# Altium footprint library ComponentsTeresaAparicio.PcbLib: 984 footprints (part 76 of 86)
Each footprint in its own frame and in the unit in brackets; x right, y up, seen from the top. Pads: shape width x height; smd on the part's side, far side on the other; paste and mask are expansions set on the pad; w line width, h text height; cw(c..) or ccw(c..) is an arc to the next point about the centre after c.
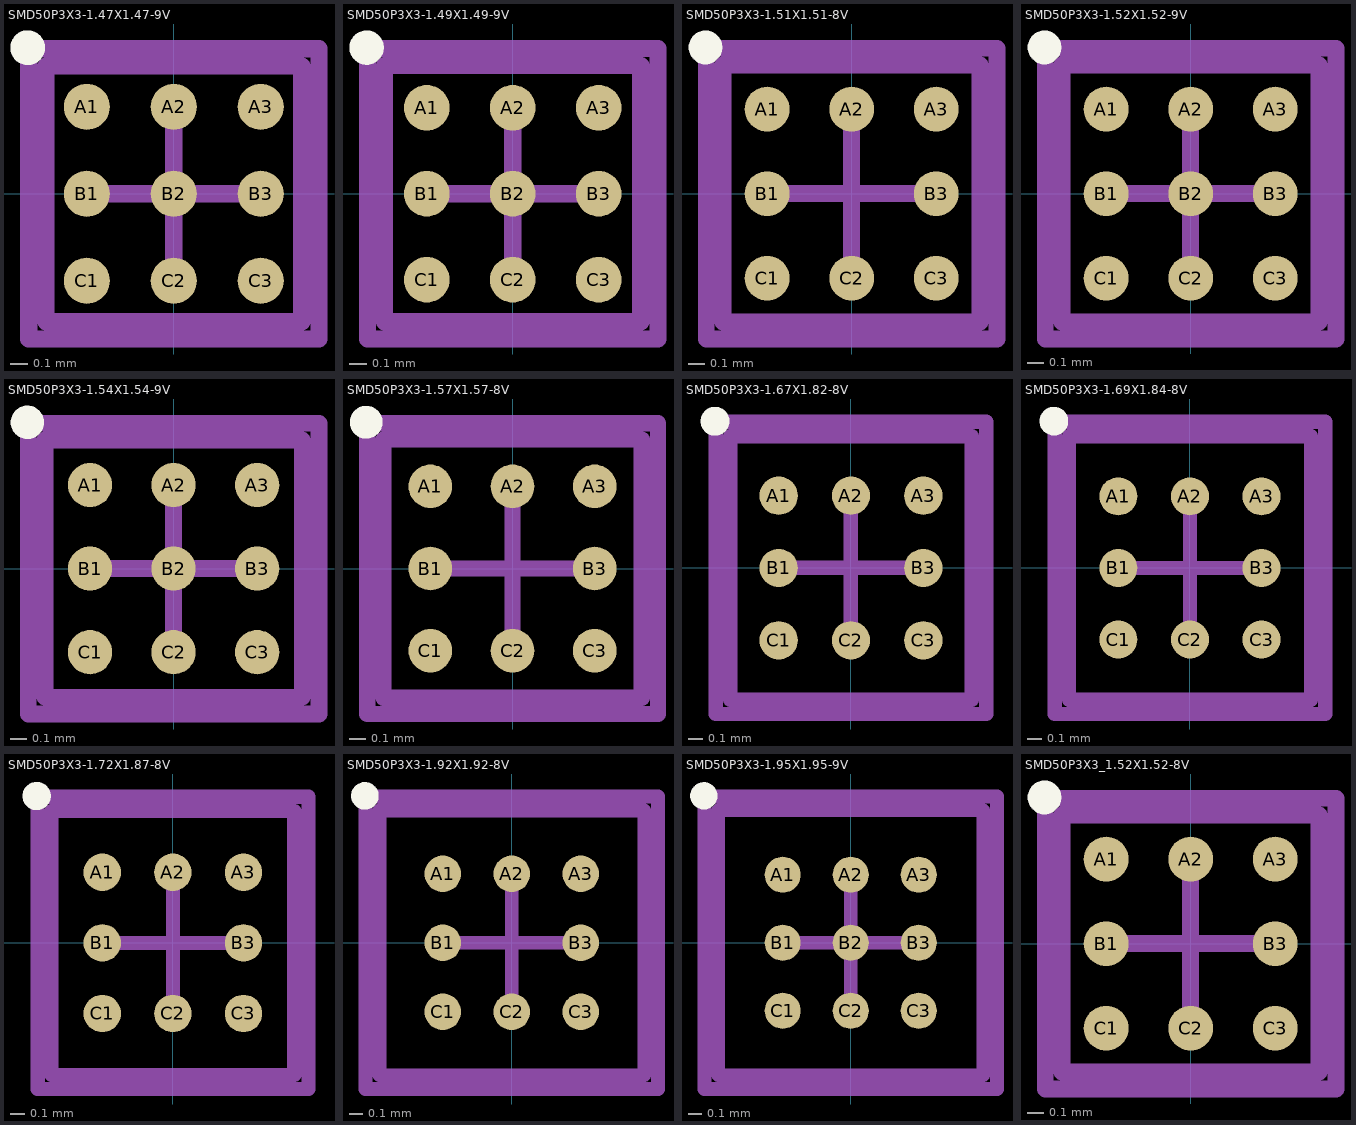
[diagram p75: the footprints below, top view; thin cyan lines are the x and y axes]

## SMD50P3X3-1.47X1.47-9V [mm] "Micro SMD, 9-Leads, Body 1.47x1.47mm, Pitch 0.5mm, NSC Recommended"
height 0.68
pads (9):
  round 0.265 smd paste-0.132 mask+0.05: A1(-0.5,0.5) A2(0,0.5) A3(0.5,0.5) B1(-0.5,0) B2(0,0) B3(0.5,0) C1(-0.5,-0.5) C2(0,-0.5) C3(0.5,-0.5)
Top Overlay:
  circle w0.1: c-0.84,0.84 r0.05
Top Paste:
  circle w0.05: c0.075,-0.6 r0.025
  circle w0.05: c-0.075,-0.45 r0.025
  circle w0.05: c-0.075,-0.6 r0.025
  circle w0.05: c0.075,-0.45 r0.025
  circle w0.05: c-0.6,-0.075 r0.025
  circle w0.05: c-0.45,0.075 r0.025
  circle w0.05: c-0.6,0.075 r0.025
  circle w0.05: c-0.45,-0.075 r0.025
  circle w0.05: c-0.075,0.6 r0.025
  circle w0.05: c0.075,0.45 r0.025
  circle w0.05: c0.075,0.6 r0.025
  circle w0.05: c-0.075,0.45 r0.025
  circle w0.05: c0.6,0.075 r0.025
  circle w0.05: c0.45,-0.075 r0.025
  circle w0.05: c0.6,-0.075 r0.025
  circle w0.05: c0.45,0.075 r0.025
  circle w0.05: c-0.45,0.45 r0.025
  circle w0.05: c-0.6,0.6 r0.025
  circle w0.05: c-0.45,0.6 r0.025
  circle w0.05: c-0.6,0.45 r0.025
  circle w0.05: c-0.45,-0.45 r0.025
  circle w0.05: c-0.6,-0.6 r0.025
  circle w0.05: c-0.6,-0.45 r0.025
  circle w0.05: c-0.45,-0.6 r0.025
  circle w0.05: c0.45,-0.45 r0.025
  circle w0.05: c0.6,-0.6 r0.025
  circle w0.05: c0.45,-0.6 r0.025
  circle w0.05: c0.6,-0.45 r0.025
  circle w0.05: c0.45,0.45 r0.025
  circle w0.05: c0.6,0.6 r0.025
  circle w0.05: c0.6,0.45 r0.025
  circle w0.05: c0.45,0.6 r0.025
  circle w0.05: c0.075,-0.075 r0.025
  circle w0.05: c-0.075,0.075 r0.025
  circle w0.05: c-0.075,-0.075 r0.025
  circle w0.05: c0.075,0.075 r0.025
  rectangle: -0.075,-0.45 0.075,-0.4
  region: -0.075,-0.6 -0.075,-0.45 -0.125,-0.45 -0.125,-0.6
  region: 0.075,-0.6 -0.075,-0.6 -0.075,-0.65 0.075,-0.65
  region: 0.075,-0.45 0.075,-0.6 0.125,-0.6 0.125,-0.45
  region: 0.075,-0.6 0.075,-0.45 -0.075,-0.45 -0.075,-0.6
  region: -0.45,0.075 -0.45,-0.075 -0.4,-0.075 -0.4,0.075
  rectangle: -0.6,0.075 -0.45,0.125
  region: -0.6,-0.075 -0.6,0.075 -0.65,0.075 -0.65,-0.075
  region: -0.45,-0.075 -0.6,-0.075 -0.6,-0.125 -0.45,-0.125
  rectangle: -0.6,-0.075 -0.45,0.075
  region: 0.075,0.45 -0.075,0.45 -0.075,0.4 0.075,0.4
  region: 0.075,0.6 0.075,0.45 0.125,0.45 0.125,0.6
  rectangle: -0.075,0.6 0.075,0.65
  region: -0.075,0.45 -0.075,0.6 -0.125,0.6 -0.125,0.45
  region: -0.075,0.6 -0.075,0.45 0.075,0.45 0.075,0.6
  region: 0.45,-0.075 0.45,0.075 0.4,0.075 0.4,-0.075
  region: 0.6,-0.075 0.45,-0.075 0.45,-0.125 0.6,-0.125
  region: 0.6,0.075 0.6,-0.075 0.65,-0.075 0.65,0.075
  rectangle: 0.45,0.075 0.6,0.125
  region: 0.6,0.075 0.45,0.075 0.45,-0.075 0.6,-0.075
  rectangle: -0.6,0.45 -0.45,0.6
  region: -0.45,0.45 -0.6,0.45 -0.6,0.4 -0.45,0.4
  region: -0.6,0.45 -0.6,0.6 -0.65,0.6 -0.65,0.45
  rectangle: -0.6,0.6 -0.45,0.65
  region: -0.45,0.6 -0.45,0.45 -0.4,0.45 -0.4,0.6
  region: -0.45,-0.6 -0.45,-0.45 -0.6,-0.45 -0.6,-0.6
  region: -0.45,-0.45 -0.45,-0.6 -0.4,-0.6 -0.4,-0.45
  region: -0.45,-0.6 -0.6,-0.6 -0.6,-0.65 -0.45,-0.65
  region: -0.6,-0.6 -0.6,-0.45 -0.65,-0.45 -0.65,-0.6
  rectangle: -0.6,-0.45 -0.45,-0.4
  region: 0.6,-0.45 0.45,-0.45 0.45,-0.6 0.6,-0.6
  rectangle: 0.45,-0.45 0.6,-0.4
  region: 0.6,-0.45 0.6,-0.6 0.65,-0.6 0.65,-0.45
  region: 0.6,-0.6 0.45,-0.6 0.45,-0.65 0.6,-0.65
  region: 0.45,-0.6 0.45,-0.45 0.4,-0.45 0.4,-0.6
  region: 0.45,0.6 0.45,0.45 0.6,0.45 0.6,0.6
  region: 0.45,0.45 0.45,0.6 0.4,0.6 0.4,0.45
  rectangle: 0.45,0.6 0.6,0.65
  region: 0.6,0.6 0.6,0.45 0.65,0.45 0.65,0.6
  region: 0.6,0.45 0.45,0.45 0.45,0.4 0.6,0.4
  region: -0.075,0.075 -0.075,-0.075 0.075,-0.075 0.075,0.075
  region: 0.125,-0.075 0.125,0.075 0.075,0.075 0.075,-0.075
  region: 0.075,0.125 -0.075,0.125 -0.075,0.075 0.075,0.075
  region: -0.125,0.075 -0.125,-0.075 -0.075,-0.075 -0.075,0.075
  rectangle: -0.075,-0.125 0.075,-0.075
Mechanical 13:
  lines w0.1: -0.735,-0.735 0.735,-0.735 0.735,0.735 -0.735,0.735 -0.735,-0.735
Mechanical 15:
  lines w0.1: -0.5,0 0.5,0 ; 0,-0.5 0,0.5 ; -0.835,-0.835 0.835,-0.835 0.835,0.835 -0.835,0.835 -0.835,-0.835
3D body: height 0.68, standoff 0, extent -0.734,-0.734 0.734,0.734

## SMD50P3X3-1.49X1.49-9V [mm] "Micro SMD, 9-Leads, Body 1.49x1.49mm, Pitch 0.5mm, NSC Recommended"
height 0.68
pads (9):
  round 0.265 smd paste-0.132 mask+0.05: A1(-0.5,0.5) A2(0,0.5) A3(0.5,0.5) B1(-0.5,0) B2(0,0) B3(0.5,0) C1(-0.5,-0.5) C2(0,-0.5) C3(0.5,-0.5)
Top Overlay:
  circle w0.1: c-0.85,0.85 r0.05
Top Paste:
  circle w0.05: c-0.6,-0.075 r0.025
  circle w0.05: c-0.45,0.075 r0.025
  circle w0.05: c-0.6,0.075 r0.025
  circle w0.05: c-0.45,-0.075 r0.025
  circle w0.05: c-0.075,0.6 r0.025
  circle w0.05: c0.075,0.45 r0.025
  circle w0.05: c0.075,0.6 r0.025
  circle w0.05: c-0.075,0.45 r0.025
  circle w0.05: c0.6,0.075 r0.025
  circle w0.05: c0.45,-0.075 r0.025
  circle w0.05: c0.6,-0.075 r0.025
  circle w0.05: c0.45,0.075 r0.025
  circle w0.05: c0.075,-0.6 r0.025
  circle w0.05: c-0.075,-0.45 r0.025
  circle w0.05: c-0.075,-0.6 r0.025
  circle w0.05: c0.075,-0.45 r0.025
  circle w0.05: c0.45,0.45 r0.025
  circle w0.05: c0.6,0.6 r0.025
  circle w0.05: c0.6,0.45 r0.025
  circle w0.05: c0.45,0.6 r0.025
  circle w0.05: c-0.45,0.45 r0.025
  circle w0.05: c-0.6,0.6 r0.025
  circle w0.05: c-0.45,0.6 r0.025
  circle w0.05: c-0.6,0.45 r0.025
  circle w0.05: c-0.45,-0.45 r0.025
  circle w0.05: c-0.6,-0.6 r0.025
  circle w0.05: c-0.6,-0.45 r0.025
  circle w0.05: c-0.45,-0.6 r0.025
  circle w0.05: c0.45,-0.45 r0.025
  circle w0.05: c0.6,-0.6 r0.025
  circle w0.05: c0.45,-0.6 r0.025
  circle w0.05: c0.6,-0.45 r0.025
  circle w0.05: c0.075,-0.075 r0.025
  circle w0.05: c-0.075,0.075 r0.025
  circle w0.05: c-0.075,-0.075 r0.025
  circle w0.05: c0.075,0.075 r0.025
  region: -0.45,0.075 -0.45,-0.075 -0.4,-0.075 -0.4,0.075
  rectangle: -0.6,0.075 -0.45,0.125
  region: -0.6,-0.075 -0.6,0.075 -0.65,0.075 -0.65,-0.075
  region: -0.45,-0.075 -0.6,-0.075 -0.6,-0.125 -0.45,-0.125
  rectangle: -0.6,-0.075 -0.45,0.075
  region: 0.075,0.45 -0.075,0.45 -0.075,0.4 0.075,0.4
  region: 0.075,0.6 0.075,0.45 0.125,0.45 0.125,0.6
  rectangle: -0.075,0.6 0.075,0.65
  region: -0.075,0.45 -0.075,0.6 -0.125,0.6 -0.125,0.45
  region: -0.075,0.6 -0.075,0.45 0.075,0.45 0.075,0.6
  region: 0.45,-0.075 0.45,0.075 0.4,0.075 0.4,-0.075
  region: 0.6,-0.075 0.45,-0.075 0.45,-0.125 0.6,-0.125
  region: 0.6,0.075 0.6,-0.075 0.65,-0.075 0.65,0.075
  rectangle: 0.45,0.075 0.6,0.125
  region: 0.6,0.075 0.45,0.075 0.45,-0.075 0.6,-0.075
  rectangle: -0.075,-0.45 0.075,-0.4
  region: -0.075,-0.6 -0.075,-0.45 -0.125,-0.45 -0.125,-0.6
  region: 0.075,-0.6 -0.075,-0.6 -0.075,-0.65 0.075,-0.65
  region: 0.075,-0.45 0.075,-0.6 0.125,-0.6 0.125,-0.45
  region: 0.075,-0.6 0.075,-0.45 -0.075,-0.45 -0.075,-0.6
  region: 0.45,0.6 0.45,0.45 0.6,0.45 0.6,0.6
  region: 0.45,0.45 0.45,0.6 0.4,0.6 0.4,0.45
  rectangle: 0.45,0.6 0.6,0.65
  region: 0.6,0.6 0.6,0.45 0.65,0.45 0.65,0.6
  region: 0.6,0.45 0.45,0.45 0.45,0.4 0.6,0.4
  rectangle: -0.6,0.45 -0.45,0.6
  region: -0.45,0.45 -0.6,0.45 -0.6,0.4 -0.45,0.4
  region: -0.6,0.45 -0.6,0.6 -0.65,0.6 -0.65,0.45
  rectangle: -0.6,0.6 -0.45,0.65
  region: -0.45,0.6 -0.45,0.45 -0.4,0.45 -0.4,0.6
  region: -0.45,-0.6 -0.45,-0.45 -0.6,-0.45 -0.6,-0.6
  region: -0.45,-0.45 -0.45,-0.6 -0.4,-0.6 -0.4,-0.45
  region: -0.45,-0.6 -0.6,-0.6 -0.6,-0.65 -0.45,-0.65
  region: -0.6,-0.6 -0.6,-0.45 -0.65,-0.45 -0.65,-0.6
  rectangle: -0.6,-0.45 -0.45,-0.4
  region: 0.6,-0.45 0.45,-0.45 0.45,-0.6 0.6,-0.6
  rectangle: 0.45,-0.45 0.6,-0.4
  region: 0.6,-0.45 0.6,-0.6 0.65,-0.6 0.65,-0.45
  region: 0.6,-0.6 0.45,-0.6 0.45,-0.65 0.6,-0.65
  region: 0.45,-0.6 0.45,-0.45 0.4,-0.45 0.4,-0.6
  region: -0.075,0.075 -0.075,-0.075 0.075,-0.075 0.075,0.075
  region: 0.125,-0.075 0.125,0.075 0.075,0.075 0.075,-0.075
  region: 0.075,0.125 -0.075,0.125 -0.075,0.075 0.075,0.075
  region: -0.125,0.075 -0.125,-0.075 -0.075,-0.075 -0.075,0.075
  rectangle: -0.075,-0.125 0.075,-0.075
Mechanical 13:
  lines w0.1: -0.745,-0.745 0.745,-0.745 0.745,0.745 -0.745,0.745 -0.745,-0.745
Mechanical 15:
  lines w0.1: -0.5,0 0.5,0 ; 0,-0.5 0,0.5 ; -0.845,-0.845 0.845,-0.845 0.845,0.845 -0.845,0.845 -0.845,-0.845
3D body: height 0.68, standoff 0, extent -0.744,-0.744 0.744,0.744

## SMD50P3X3-1.51X1.51-8V [mm] "Micro SMD, 8-Leads, Body 1.51x1.51mm, Pitch 0.5mm, NSC Recommended"
height 1.1
pads (8):
  round 0.265 smd paste-0.132 mask+0.05: A1(-0.5,0.5) A2(0,0.5) A3(0.5,0.5) B1(-0.5,0) B3(0.5,0) C1(-0.5,-0.5) C2(0,-0.5) C3(0.5,-0.5)
Top Overlay:
  circle w0.1: c-0.865,0.865 r0.05
Top Paste:
  circle w0.05: c-0.075,0.6 r0.025
  circle w0.05: c0.075,0.45 r0.025
  circle w0.05: c0.075,0.6 r0.025
  circle w0.05: c-0.075,0.45 r0.025
  circle w0.05: c0.6,0.075 r0.025
  circle w0.05: c0.45,-0.075 r0.025
  circle w0.05: c0.6,-0.075 r0.025
  circle w0.05: c0.45,0.075 r0.025
  circle w0.05: c0.075,-0.6 r0.025
  circle w0.05: c-0.075,-0.45 r0.025
  circle w0.05: c-0.075,-0.6 r0.025
  circle w0.05: c0.075,-0.45 r0.025
  circle w0.05: c-0.6,-0.075 r0.025
  circle w0.05: c-0.45,0.075 r0.025
  circle w0.05: c-0.6,0.075 r0.025
  circle w0.05: c-0.45,-0.075 r0.025
  circle w0.05: c0.45,0.45 r0.025
  circle w0.05: c0.6,0.6 r0.025
  circle w0.05: c0.6,0.45 r0.025
  circle w0.05: c0.45,0.6 r0.025
  circle w0.05: c0.45,-0.45 r0.025
  circle w0.05: c0.6,-0.6 r0.025
  circle w0.05: c0.45,-0.6 r0.025
  circle w0.05: c0.6,-0.45 r0.025
  circle w0.05: c-0.45,-0.45 r0.025
  circle w0.05: c-0.6,-0.6 r0.025
  circle w0.05: c-0.6,-0.45 r0.025
  circle w0.05: c-0.45,-0.6 r0.025
  circle w0.05: c-0.45,0.45 r0.025
  circle w0.05: c-0.6,0.6 r0.025
  circle w0.05: c-0.45,0.6 r0.025
  circle w0.05: c-0.6,0.45 r0.025
  region: 0.075,0.45 -0.075,0.45 -0.075,0.4 0.075,0.4
  region: 0.075,0.6 0.075,0.45 0.125,0.45 0.125,0.6
  rectangle: -0.075,0.6 0.075,0.65
  region: -0.075,0.45 -0.075,0.6 -0.125,0.6 -0.125,0.45
  region: -0.075,0.6 -0.075,0.45 0.075,0.45 0.075,0.6
  region: 0.45,-0.075 0.45,0.075 0.4,0.075 0.4,-0.075
  region: 0.6,-0.075 0.45,-0.075 0.45,-0.125 0.6,-0.125
  region: 0.6,0.075 0.6,-0.075 0.65,-0.075 0.65,0.075
  rectangle: 0.45,0.075 0.6,0.125
  region: 0.6,0.075 0.45,0.075 0.45,-0.075 0.6,-0.075
  rectangle: -0.075,-0.45 0.075,-0.4
  region: -0.075,-0.6 -0.075,-0.45 -0.125,-0.45 -0.125,-0.6
  region: 0.075,-0.6 -0.075,-0.6 -0.075,-0.65 0.075,-0.65
  region: 0.075,-0.45 0.075,-0.6 0.125,-0.6 0.125,-0.45
  region: 0.075,-0.6 0.075,-0.45 -0.075,-0.45 -0.075,-0.6
  region: -0.45,0.075 -0.45,-0.075 -0.4,-0.075 -0.4,0.075
  rectangle: -0.6,0.075 -0.45,0.125
  region: -0.6,-0.075 -0.6,0.075 -0.65,0.075 -0.65,-0.075
  region: -0.45,-0.075 -0.6,-0.075 -0.6,-0.125 -0.45,-0.125
  rectangle: -0.6,-0.075 -0.45,0.075
  region: 0.45,0.6 0.45,0.45 0.6,0.45 0.6,0.6
  region: 0.45,0.45 0.45,0.6 0.4,0.6 0.4,0.45
  rectangle: 0.45,0.6 0.6,0.65
  region: 0.6,0.6 0.6,0.45 0.65,0.45 0.65,0.6
  region: 0.6,0.45 0.45,0.45 0.45,0.4 0.6,0.4
  region: 0.6,-0.45 0.45,-0.45 0.45,-0.6 0.6,-0.6
  rectangle: 0.45,-0.45 0.6,-0.4
  region: 0.6,-0.45 0.6,-0.6 0.65,-0.6 0.65,-0.45
  region: 0.6,-0.6 0.45,-0.6 0.45,-0.65 0.6,-0.65
  region: 0.45,-0.6 0.45,-0.45 0.4,-0.45 0.4,-0.6
  region: -0.45,-0.6 -0.45,-0.45 -0.6,-0.45 -0.6,-0.6
  region: -0.45,-0.45 -0.45,-0.6 -0.4,-0.6 -0.4,-0.45
  region: -0.45,-0.6 -0.6,-0.6 -0.6,-0.65 -0.45,-0.65
  region: -0.6,-0.6 -0.6,-0.45 -0.65,-0.45 -0.65,-0.6
  rectangle: -0.6,-0.45 -0.45,-0.4
  rectangle: -0.6,0.45 -0.45,0.6
  region: -0.45,0.45 -0.6,0.45 -0.6,0.4 -0.45,0.4
  region: -0.6,0.45 -0.6,0.6 -0.65,0.6 -0.65,0.45
  rectangle: -0.6,0.6 -0.45,0.65
  region: -0.45,0.6 -0.45,0.45 -0.4,0.45 -0.4,0.6
Mechanical 13:
  lines w0.1: -0.76,-0.76 -0.76,0.76 0.76,0.76 0.76,-0.76 -0.76,-0.76
Mechanical 15:
  lines w0.1: -0.5,0 0.5,0 ; 0,-0.5 0,0.5 ; -0.86,-0.86 -0.86,0.86 0.86,0.86 0.86,-0.86 -0.86,-0.86
3D body: height 1.1, standoff 0, extent -0.759,-0.759 0.759,0.759

## SMD50P3X3-1.52X1.52-9V [mm] "Micro SMD, 9-Leads, Body 1.52x1.52mm, Pitch 0.5mm, NSC Recommended"
height 0.68
pads (9):
  round 0.265 smd paste-0.132 mask+0.05: A1(-0.5,0.5) A2(0,0.5) A3(0.5,0.5) B1(-0.5,0) B2(0,0) B3(0.5,0) C1(-0.5,-0.5) C2(0,-0.5) C3(0.5,-0.5)
Top Overlay:
  circle w0.1: c-0.865,0.865 r0.05
Top Paste:
  circle w0.05: c0.075,0.075 r0.025
  circle w0.05: c-0.075,-0.075 r0.025
  circle w0.05: c-0.075,0.075 r0.025
  circle w0.05: c0.075,-0.075 r0.025
  circle w0.05: c0.45,-0.45 r0.025
  circle w0.05: c0.6,-0.6 r0.025
  circle w0.05: c0.45,-0.6 r0.025
  circle w0.05: c0.6,-0.45 r0.025
  circle w0.05: c0.45,0.45 r0.025
  circle w0.05: c0.6,0.6 r0.025
  circle w0.05: c0.6,0.45 r0.025
  circle w0.05: c0.45,0.6 r0.025
  circle w0.05: c-0.45,0.45 r0.025
  circle w0.05: c-0.6,0.6 r0.025
  circle w0.05: c-0.45,0.6 r0.025
  circle w0.05: c-0.6,0.45 r0.025
  circle w0.05: c-0.45,-0.45 r0.025
  circle w0.05: c-0.6,-0.6 r0.025
  circle w0.05: c-0.6,-0.45 r0.025
  circle w0.05: c-0.45,-0.6 r0.025
  circle w0.05: c-0.45,-0.075 r0.025
  circle w0.05: c-0.6,0.075 r0.025
  circle w0.05: c-0.45,0.075 r0.025
  circle w0.05: c-0.6,-0.075 r0.025
  circle w0.05: c0.075,-0.45 r0.025
  circle w0.05: c-0.075,-0.6 r0.025
  circle w0.05: c-0.075,-0.45 r0.025
  circle w0.05: c0.075,-0.6 r0.025
  circle w0.05: c0.45,0.075 r0.025
  circle w0.05: c0.6,-0.075 r0.025
  circle w0.05: c0.45,-0.075 r0.025
  circle w0.05: c0.6,0.075 r0.025
  circle w0.05: c-0.075,0.45 r0.025
  circle w0.05: c0.075,0.6 r0.025
  circle w0.05: c0.075,0.45 r0.025
  circle w0.05: c-0.075,0.6 r0.025
  rectangle: -0.075,-0.125 0.075,-0.075
  region: -0.125,0.075 -0.125,-0.075 -0.075,-0.075 -0.075,0.075
  region: 0.075,0.125 -0.075,0.125 -0.075,0.075 0.075,0.075
  region: 0.125,-0.075 0.125,0.075 0.075,0.075 0.075,-0.075
  region: -0.075,0.075 -0.075,-0.075 0.075,-0.075 0.075,0.075
  region: 0.6,-0.45 0.45,-0.45 0.45,-0.6 0.6,-0.6
  rectangle: 0.45,-0.45 0.6,-0.4
  region: 0.6,-0.45 0.6,-0.6 0.65,-0.6 0.65,-0.45
  region: 0.6,-0.6 0.45,-0.6 0.45,-0.65 0.6,-0.65
  region: 0.45,-0.6 0.45,-0.45 0.4,-0.45 0.4,-0.6
  region: 0.45,0.6 0.45,0.45 0.6,0.45 0.6,0.6
  region: 0.45,0.45 0.45,0.6 0.4,0.6 0.4,0.45
  rectangle: 0.45,0.6 0.6,0.65
  region: 0.6,0.6 0.6,0.45 0.65,0.45 0.65,0.6
  region: 0.6,0.45 0.45,0.45 0.45,0.4 0.6,0.4
  rectangle: -0.6,0.45 -0.45,0.6
  region: -0.45,0.45 -0.6,0.45 -0.6,0.4 -0.45,0.4
  region: -0.6,0.45 -0.6,0.6 -0.65,0.6 -0.65,0.45
  rectangle: -0.6,0.6 -0.45,0.65
  region: -0.45,0.6 -0.45,0.45 -0.4,0.45 -0.4,0.6
  region: -0.45,-0.6 -0.45,-0.45 -0.6,-0.45 -0.6,-0.6
  region: -0.45,-0.45 -0.45,-0.6 -0.4,-0.6 -0.4,-0.45
  region: -0.45,-0.6 -0.6,-0.6 -0.6,-0.65 -0.45,-0.65
  region: -0.6,-0.6 -0.6,-0.45 -0.65,-0.45 -0.65,-0.6
  rectangle: -0.6,-0.45 -0.45,-0.4
  rectangle: -0.6,-0.075 -0.45,0.075
  region: -0.45,-0.075 -0.6,-0.075 -0.6,-0.125 -0.45,-0.125
  region: -0.6,-0.075 -0.6,0.075 -0.65,0.075 -0.65,-0.075
  rectangle: -0.6,0.075 -0.45,0.125
  region: -0.45,0.075 -0.45,-0.075 -0.4,-0.075 -0.4,0.075
  region: 0.075,-0.6 0.075,-0.45 -0.075,-0.45 -0.075,-0.6
  region: 0.075,-0.45 0.075,-0.6 0.125,-0.6 0.125,-0.45
  region: 0.075,-0.6 -0.075,-0.6 -0.075,-0.65 0.075,-0.65
  region: -0.075,-0.6 -0.075,-0.45 -0.125,-0.45 -0.125,-0.6
  rectangle: -0.075,-0.45 0.075,-0.4
  region: 0.6,0.075 0.45,0.075 0.45,-0.075 0.6,-0.075
  rectangle: 0.45,0.075 0.6,0.125
  region: 0.6,0.075 0.6,-0.075 0.65,-0.075 0.65,0.075
  region: 0.6,-0.075 0.45,-0.075 0.45,-0.125 0.6,-0.125
  region: 0.45,-0.075 0.45,0.075 0.4,0.075 0.4,-0.075
  region: -0.075,0.6 -0.075,0.45 0.075,0.45 0.075,0.6
  region: -0.075,0.45 -0.075,0.6 -0.125,0.6 -0.125,0.45
  rectangle: -0.075,0.6 0.075,0.65
  region: 0.075,0.6 0.075,0.45 0.125,0.45 0.125,0.6
  region: 0.075,0.45 -0.075,0.45 -0.075,0.4 0.075,0.4
Mechanical 13:
  lines w0.1: -0.76,-0.76 -0.76,0.76 0.76,0.76 0.76,-0.76 -0.76,-0.76
Mechanical 15:
  lines w0.1: -0.5,0 0.5,0 ; 0,-0.5 0,0.5 ; -0.86,-0.86 -0.86,0.86 0.86,0.86 0.86,-0.86 -0.86,-0.86
3D body: height 0.68, standoff 0, extent -0.759,-0.759 0.759,0.759

## SMD50P3X3-1.54X1.54-9V [mm] "Micro SMD, 9-Leads, Body 1.54x1.54mm, Pitch 0.5mm, NSC Recommended"
height 0.68
pads (9):
  round 0.265 smd paste-0.132 mask+0.05: A1(-0.5,0.5) A2(0,0.5) A3(0.5,0.5) B1(-0.5,0) B2(0,0) B3(0.5,0) C1(-0.5,-0.5) C2(0,-0.5) C3(0.5,-0.5)
Top Overlay:
  circle w0.1: c-0.875,0.875 r0.05
Top Paste:
  circle w0.05: c-0.6,0.45 r0.025
  circle w0.05: c-0.45,0.6 r0.025
  circle w0.05: c-0.45,0.45 r0.025
  circle w0.05: c-0.6,0.6 r0.025
  circle w0.05: c-0.075,0.45 r0.025
  circle w0.05: c0.075,0.6 r0.025
  circle w0.05: c0.075,0.45 r0.025
  circle w0.05: c-0.075,0.6 r0.025
  circle w0.05: c0.45,0.45 r0.025
  circle w0.05: c0.6,0.6 r0.025
  circle w0.05: c0.6,0.45 r0.025
  circle w0.05: c0.45,0.6 r0.025
  circle w0.05: c-0.6,-0.075 r0.025
  circle w0.05: c-0.45,0.075 r0.025
  circle w0.05: c-0.45,-0.075 r0.025
  circle w0.05: c-0.6,0.075 r0.025
  circle w0.05: c-0.075,-0.075 r0.025
  circle w0.05: c0.075,0.075 r0.025
  circle w0.05: c0.075,-0.075 r0.025
  circle w0.05: c-0.075,0.075 r0.025
  circle w0.05: c0.45,-0.075 r0.025
  circle w0.05: c0.6,0.075 r0.025
  circle w0.05: c0.6,-0.075 r0.025
  circle w0.05: c0.45,0.075 r0.025
  circle w0.05: c-0.6,-0.6 r0.025
  circle w0.05: c-0.45,-0.45 r0.025
  circle w0.05: c-0.45,-0.6 r0.025
  circle w0.05: c-0.6,-0.45 r0.025
  circle w0.05: c-0.075,-0.6 r0.025
  circle w0.05: c0.075,-0.45 r0.025
  circle w0.05: c0.075,-0.6 r0.025
  circle w0.05: c-0.075,-0.45 r0.025
  circle w0.05: c0.45,-0.6 r0.025
  circle w0.05: c0.6,-0.45 r0.025
  circle w0.05: c0.6,-0.6 r0.025
  circle w0.05: c0.45,-0.45 r0.025
  region: -0.6,0.6 -0.6,0.45 -0.45,0.45 -0.45,0.6
  region: -0.6,0.45 -0.6,0.6 -0.65,0.6 -0.65,0.45
  rectangle: -0.6,0.6 -0.45,0.65
  region: -0.45,0.6 -0.45,0.45 -0.4,0.45 -0.4,0.6
  region: -0.45,0.45 -0.6,0.45 -0.6,0.4 -0.45,0.4
  region: -0.075,0.6 -0.075,0.45 0.075,0.45 0.075,0.6
  region: -0.075,0.45 -0.075,0.6 -0.125,0.6 -0.125,0.45
  rectangle: -0.075,0.6 0.075,0.65
  region: 0.075,0.6 0.075,0.45 0.125,0.45 0.125,0.6
  region: 0.075,0.45 -0.075,0.45 -0.075,0.4 0.075,0.4
  region: 0.45,0.6 0.45,0.45 0.6,0.45 0.6,0.6
  region: 0.45,0.45 0.45,0.6 0.4,0.6 0.4,0.45
  rectangle: 0.45,0.6 0.6,0.65
  region: 0.6,0.6 0.6,0.45 0.65,0.45 0.65,0.6
  region: 0.6,0.45 0.45,0.45 0.45,0.4 0.6,0.4
  region: -0.6,0.075 -0.6,-0.075 -0.45,-0.075 -0.45,0.075
  region: -0.6,-0.075 -0.6,0.075 -0.65,0.075 -0.65,-0.075
  rectangle: -0.6,0.075 -0.45,0.125
  region: -0.45,0.075 -0.45,-0.075 -0.4,-0.075 -0.4,0.075
  region: -0.45,-0.075 -0.6,-0.075 -0.6,-0.125 -0.45,-0.125
  region: -0.075,0.075 -0.075,-0.075 0.075,-0.075 0.075,0.075
  region: -0.075,-0.075 -0.075,0.075 -0.125,0.075 -0.125,-0.075
  rectangle: -0.075,0.075 0.075,0.125
  region: 0.075,0.075 0.075,-0.075 0.125,-0.075 0.125,0.075
  region: 0.075,-0.075 -0.075,-0.075 -0.075,-0.125 0.075,-0.125
  region: 0.45,0.075 0.45,-0.075 0.6,-0.075 0.6,0.075
  region: 0.45,-0.075 0.45,0.075 0.4,0.075 0.4,-0.075
  rectangle: 0.45,0.075 0.6,0.125
  region: 0.6,0.075 0.6,-0.075 0.65,-0.075 0.65,0.075
  region: 0.6,-0.075 0.45,-0.075 0.45,-0.125 0.6,-0.125
  region: -0.6,-0.45 -0.6,-0.6 -0.45,-0.6 -0.45,-0.45
  region: -0.6,-0.6 -0.6,-0.45 -0.65,-0.45 -0.65,-0.6
  rectangle: -0.6,-0.45 -0.45,-0.4
  region: -0.45,-0.45 -0.45,-0.6 -0.4,-0.6 -0.4,-0.45
  region: -0.45,-0.6 -0.6,-0.6 -0.6,-0.65 -0.45,-0.65
  region: -0.075,-0.45 -0.075,-0.6 0.075,-0.6 0.075,-0.45
  region: -0.075,-0.6 -0.075,-0.45 -0.125,-0.45 -0.125,-0.6
  rectangle: -0.075,-0.45 0.075,-0.4
  region: 0.075,-0.45 0.075,-0.6 0.125,-0.6 0.125,-0.45
  region: 0.075,-0.6 -0.075,-0.6 -0.075,-0.65 0.075,-0.65
  region: 0.45,-0.45 0.45,-0.6 0.6,-0.6 0.6,-0.45
  region: 0.45,-0.6 0.45,-0.45 0.4,-0.45 0.4,-0.6
  rectangle: 0.45,-0.45 0.6,-0.4
  region: 0.6,-0.45 0.6,-0.6 0.65,-0.6 0.65,-0.45
  region: 0.6,-0.6 0.45,-0.6 0.45,-0.65 0.6,-0.65
Mechanical 13:
  lines w0.1: -0.77,-0.77 -0.77,0.77 0.77,0.77 0.77,-0.77 -0.77,-0.77
Mechanical 15:
  lines w0.1: -0.5,0 0.5,0 ; 0,-0.5 0,0.5 ; -0.87,-0.87 -0.87,0.87 0.87,0.87 0.87,-0.87 -0.87,-0.87
3D body: height 0.68, standoff 0, extent -0.77,-0.77 0.77,0.77

## SMD50P3X3-1.57X1.57-8V [mm] "Micro SMD, 8-Leads, Body 1.57x1.57mm, Pitch 0.5mm, NSC Recommended"
height 0.68
pads (8):
  round 0.265 smd paste-0.132 mask+0.05: A1(-0.5,0.5) A2(0,0.5) A3(0.5,0.5) B1(-0.5,0) B3(0.5,0) C1(-0.5,-0.5) C2(0,-0.5) C3(0.5,-0.5)
Top Overlay:
  circle w0.1: c-0.89,0.89 r0.05
Top Paste:
  circle w0.05: c-0.075,0.6 r0.025
  circle w0.05: c0.075,0.45 r0.025
  circle w0.05: c0.075,0.6 r0.025
  circle w0.05: c-0.075,0.45 r0.025
  circle w0.05: c0.6,0.075 r0.025
  circle w0.05: c0.45,-0.075 r0.025
  circle w0.05: c0.6,-0.075 r0.025
  circle w0.05: c0.45,0.075 r0.025
  circle w0.05: c0.075,-0.6 r0.025
  circle w0.05: c-0.075,-0.45 r0.025
  circle w0.05: c-0.075,-0.6 r0.025
  circle w0.05: c0.075,-0.45 r0.025
  circle w0.05: c-0.6,-0.075 r0.025
  circle w0.05: c-0.45,0.075 r0.025
  circle w0.05: c-0.6,0.075 r0.025
  circle w0.05: c-0.45,-0.075 r0.025
  circle w0.05: c0.45,0.45 r0.025
  circle w0.05: c0.6,0.6 r0.025
  circle w0.05: c0.6,0.45 r0.025
  circle w0.05: c0.45,0.6 r0.025
  circle w0.05: c0.45,-0.45 r0.025
  circle w0.05: c0.6,-0.6 r0.025
  circle w0.05: c0.45,-0.6 r0.025
  circle w0.05: c0.6,-0.45 r0.025
  circle w0.05: c-0.45,-0.45 r0.025
  circle w0.05: c-0.6,-0.6 r0.025
  circle w0.05: c-0.6,-0.45 r0.025
  circle w0.05: c-0.45,-0.6 r0.025
  circle w0.05: c-0.45,0.45 r0.025
  circle w0.05: c-0.6,0.6 r0.025
  circle w0.05: c-0.45,0.6 r0.025
  circle w0.05: c-0.6,0.45 r0.025
  region: 0.075,0.45 -0.075,0.45 -0.075,0.4 0.075,0.4
  region: 0.075,0.6 0.075,0.45 0.125,0.45 0.125,0.6
  rectangle: -0.075,0.6 0.075,0.65
  region: -0.075,0.45 -0.075,0.6 -0.125,0.6 -0.125,0.45
  region: -0.075,0.6 -0.075,0.45 0.075,0.45 0.075,0.6
  region: 0.45,-0.075 0.45,0.075 0.4,0.075 0.4,-0.075
  region: 0.6,-0.075 0.45,-0.075 0.45,-0.125 0.6,-0.125
  region: 0.6,0.075 0.6,-0.075 0.65,-0.075 0.65,0.075
  rectangle: 0.45,0.075 0.6,0.125
  region: 0.6,0.075 0.45,0.075 0.45,-0.075 0.6,-0.075
  rectangle: -0.075,-0.45 0.075,-0.4
  region: -0.075,-0.6 -0.075,-0.45 -0.125,-0.45 -0.125,-0.6
  region: 0.075,-0.6 -0.075,-0.6 -0.075,-0.65 0.075,-0.65
  region: 0.075,-0.45 0.075,-0.6 0.125,-0.6 0.125,-0.45
  region: 0.075,-0.6 0.075,-0.45 -0.075,-0.45 -0.075,-0.6
  region: -0.45,0.075 -0.45,-0.075 -0.4,-0.075 -0.4,0.075
  rectangle: -0.6,0.075 -0.45,0.125
  region: -0.6,-0.075 -0.6,0.075 -0.65,0.075 -0.65,-0.075
  region: -0.45,-0.075 -0.6,-0.075 -0.6,-0.125 -0.45,-0.125
  rectangle: -0.6,-0.075 -0.45,0.075
  region: 0.45,0.6 0.45,0.45 0.6,0.45 0.6,0.6
  region: 0.45,0.45 0.45,0.6 0.4,0.6 0.4,0.45
  rectangle: 0.45,0.6 0.6,0.65
  region: 0.6,0.6 0.6,0.45 0.65,0.45 0.65,0.6
  region: 0.6,0.45 0.45,0.45 0.45,0.4 0.6,0.4
  region: 0.6,-0.45 0.45,-0.45 0.45,-0.6 0.6,-0.6
  rectangle: 0.45,-0.45 0.6,-0.4
  region: 0.6,-0.45 0.6,-0.6 0.65,-0.6 0.65,-0.45
  region: 0.6,-0.6 0.45,-0.6 0.45,-0.65 0.6,-0.65
  region: 0.45,-0.6 0.45,-0.45 0.4,-0.45 0.4,-0.6
  region: -0.45,-0.6 -0.45,-0.45 -0.6,-0.45 -0.6,-0.6
  region: -0.45,-0.45 -0.45,-0.6 -0.4,-0.6 -0.4,-0.45
  region: -0.45,-0.6 -0.6,-0.6 -0.6,-0.65 -0.45,-0.65
  region: -0.6,-0.6 -0.6,-0.45 -0.65,-0.45 -0.65,-0.6
  rectangle: -0.6,-0.45 -0.45,-0.4
  rectangle: -0.6,0.45 -0.45,0.6
  region: -0.45,0.45 -0.6,0.45 -0.6,0.4 -0.45,0.4
  region: -0.6,0.45 -0.6,0.6 -0.65,0.6 -0.65,0.45
  rectangle: -0.6,0.6 -0.45,0.65
  region: -0.45,0.6 -0.45,0.45 -0.4,0.45 -0.4,0.6
Mechanical 13:
  lines w0.1: -0.785,-0.785 0.785,-0.785 0.785,0.785 -0.785,0.785 -0.785,-0.785
Mechanical 15:
  lines w0.1: -0.5,0 0.5,0 ; 0,-0.5 0,0.5 ; -0.885,-0.885 0.885,-0.885 0.885,0.885 -0.885,0.885 -0.885,-0.885
3D body: height 0.68, standoff 0, extent -0.784,-0.784 0.784,0.784

## SMD50P3X3-1.67X1.82-8V [mm] "Micro SMD, 8-Leads, Body 1.82x1.67mm, Pitch 0.5mm, NSC Recommended"
height 0.68
pads (8):
  round 0.265 smd paste-0.132 mask+0.05: A1(-0.5,0.5) A2(0,0.5) A3(0.5,0.5) B1(-0.5,0) B3(0.5,0) C1(-0.5,-0.5) C2(0,-0.5) C3(0.5,-0.5)
Top Overlay:
  circle w0.1: c-0.94,1.015 r0.05
Top Paste:
  circle w0.05: c-0.6,0.45 r0.025
  circle w0.05: c-0.45,0.6 r0.025
  circle w0.05: c-0.45,0.45 r0.025
  circle w0.05: c-0.6,0.6 r0.025
  circle w0.05: c-0.075,0.45 r0.025
  circle w0.05: c0.075,0.6 r0.025
  circle w0.05: c0.075,0.45 r0.025
  circle w0.05: c-0.075,0.6 r0.025
  circle w0.05: c0.45,0.45 r0.025
  circle w0.05: c0.6,0.6 r0.025
  circle w0.05: c0.6,0.45 r0.025
  circle w0.05: c0.45,0.6 r0.025
  circle w0.05: c-0.6,-0.075 r0.025
  circle w0.05: c-0.45,0.075 r0.025
  circle w0.05: c-0.45,-0.075 r0.025
  circle w0.05: c-0.6,0.075 r0.025
  circle w0.05: c0.45,-0.075 r0.025
  circle w0.05: c0.6,0.075 r0.025
  circle w0.05: c0.6,-0.075 r0.025
  circle w0.05: c0.45,0.075 r0.025
  circle w0.05: c-0.6,-0.6 r0.025
  circle w0.05: c-0.45,-0.45 r0.025
  circle w0.05: c-0.45,-0.6 r0.025
  circle w0.05: c-0.6,-0.45 r0.025
  circle w0.05: c-0.075,-0.6 r0.025
  circle w0.05: c0.075,-0.45 r0.025
  circle w0.05: c0.075,-0.6 r0.025
  circle w0.05: c-0.075,-0.45 r0.025
  circle w0.05: c0.45,-0.6 r0.025
  circle w0.05: c0.6,-0.45 r0.025
  circle w0.05: c0.6,-0.6 r0.025
  circle w0.05: c0.45,-0.45 r0.025
  region: -0.6,0.6 -0.6,0.45 -0.45,0.45 -0.45,0.6
  region: -0.6,0.45 -0.6,0.6 -0.65,0.6 -0.65,0.45
  rectangle: -0.6,0.6 -0.45,0.65
  region: -0.45,0.6 -0.45,0.45 -0.4,0.45 -0.4,0.6
  region: -0.45,0.45 -0.6,0.45 -0.6,0.4 -0.45,0.4
  region: -0.075,0.6 -0.075,0.45 0.075,0.45 0.075,0.6
  region: -0.075,0.45 -0.075,0.6 -0.125,0.6 -0.125,0.45
  rectangle: -0.075,0.6 0.075,0.65
  region: 0.075,0.6 0.075,0.45 0.125,0.45 0.125,0.6
  region: 0.075,0.45 -0.075,0.45 -0.075,0.4 0.075,0.4
  region: 0.45,0.6 0.45,0.45 0.6,0.45 0.6,0.6
  region: 0.45,0.45 0.45,0.6 0.4,0.6 0.4,0.45
  rectangle: 0.45,0.6 0.6,0.65
  region: 0.6,0.6 0.6,0.45 0.65,0.45 0.65,0.6
  region: 0.6,0.45 0.45,0.45 0.45,0.4 0.6,0.4
  region: -0.6,0.075 -0.6,-0.075 -0.45,-0.075 -0.45,0.075
  region: -0.6,-0.075 -0.6,0.075 -0.65,0.075 -0.65,-0.075
  rectangle: -0.6,0.075 -0.45,0.125
  region: -0.45,0.075 -0.45,-0.075 -0.4,-0.075 -0.4,0.075
  region: -0.45,-0.075 -0.6,-0.075 -0.6,-0.125 -0.45,-0.125
  region: 0.45,0.075 0.45,-0.075 0.6,-0.075 0.6,0.075
  region: 0.45,-0.075 0.45,0.075 0.4,0.075 0.4,-0.075
  rectangle: 0.45,0.075 0.6,0.125
  region: 0.6,0.075 0.6,-0.075 0.65,-0.075 0.65,0.075
  region: 0.6,-0.075 0.45,-0.075 0.45,-0.125 0.6,-0.125
  region: -0.6,-0.45 -0.6,-0.6 -0.45,-0.6 -0.45,-0.45
  region: -0.6,-0.6 -0.6,-0.45 -0.65,-0.45 -0.65,-0.6
  rectangle: -0.6,-0.45 -0.45,-0.4
  region: -0.45,-0.45 -0.45,-0.6 -0.4,-0.6 -0.4,-0.45
  region: -0.45,-0.6 -0.6,-0.6 -0.6,-0.65 -0.45,-0.65
  region: -0.075,-0.45 -0.075,-0.6 0.075,-0.6 0.075,-0.45
  region: -0.075,-0.6 -0.075,-0.45 -0.125,-0.45 -0.125,-0.6
  rectangle: -0.075,-0.45 0.075,-0.4
  region: 0.075,-0.45 0.075,-0.6 0.125,-0.6 0.125,-0.45
  region: 0.075,-0.6 -0.075,-0.6 -0.075,-0.65 0.075,-0.65
  region: 0.45,-0.45 0.45,-0.6 0.6,-0.6 0.6,-0.45
  region: 0.45,-0.6 0.45,-0.45 0.4,-0.45 0.4,-0.6
  rectangle: 0.45,-0.45 0.6,-0.4
  region: 0.6,-0.45 0.6,-0.6 0.65,-0.6 0.65,-0.45
  region: 0.6,-0.6 0.45,-0.6 0.45,-0.65 0.6,-0.65
Mechanical 13:
  lines w0.1: -0.835,-0.91 -0.835,0.91 0.835,0.91 0.835,-0.91 -0.835,-0.91
Mechanical 15:
  lines w0.1: -0.5,0 0.5,0 ; 0,-0.5 0,0.5 ; -0.935,-1.01 -0.935,1.01 0.935,1.01 0.935,-1.01 -0.935,-1.01
3D body: height 0.68, standoff 0, extent -0.835,-0.91 0.835,0.91

## SMD50P3X3-1.69X1.84-8V [mm] "Micro SMD, 8-Leads, Body 1.84x1.69mm, Pitch 0.5mm, NSC Recommended"
height 0.68
pads (8):
  round 0.265 smd paste-0.132 mask+0.05: A1(-0.5,0.5) A2(0,0.5) A3(0.5,0.5) B1(-0.5,0) B3(0.5,0) C1(-0.5,-0.5) C2(0,-0.5) C3(0.5,-0.5)
Top Overlay:
  circle w0.1: c-0.95,1.025 r0.05
Top Paste:
  circle w0.05: c0.45,-0.45 r0.025
  circle w0.05: c0.6,-0.6 r0.025
  circle w0.05: c0.6,-0.45 r0.025
  circle w0.05: c0.45,-0.6 r0.025
  circle w0.05: c-0.075,-0.45 r0.025
  circle w0.05: c0.075,-0.6 r0.025
  circle w0.05: c0.075,-0.45 r0.025
  circle w0.05: c-0.075,-0.6 r0.025
  circle w0.05: c-0.6,-0.45 r0.025
  circle w0.05: c-0.45,-0.6 r0.025
  circle w0.05: c-0.45,-0.45 r0.025
  circle w0.05: c-0.6,-0.6 r0.025
  circle w0.05: c0.45,0.075 r0.025
  circle w0.05: c0.6,-0.075 r0.025
  circle w0.05: c0.6,0.075 r0.025
  circle w0.05: c0.45,-0.075 r0.025
  circle w0.05: c-0.6,0.075 r0.025
  circle w0.05: c-0.45,-0.075 r0.025
  circle w0.05: c-0.45,0.075 r0.025
  circle w0.05: c-0.6,-0.075 r0.025
  circle w0.05: c0.45,0.6 r0.025
  circle w0.05: c0.6,0.45 r0.025
  circle w0.05: c0.6,0.6 r0.025
  circle w0.05: c0.45,0.45 r0.025
  circle w0.05: c-0.075,0.6 r0.025
  circle w0.05: c0.075,0.45 r0.025
  circle w0.05: c0.075,0.6 r0.025
  circle w0.05: c-0.075,0.45 r0.025
  circle w0.05: c-0.6,0.6 r0.025
  circle w0.05: c-0.45,0.45 r0.025
  circle w0.05: c-0.45,0.6 r0.025
  circle w0.05: c-0.6,0.45 r0.025
  region: 0.6,-0.6 0.45,-0.6 0.45,-0.65 0.6,-0.65
  region: 0.6,-0.45 0.6,-0.6 0.65,-0.6 0.65,-0.45
  rectangle: 0.45,-0.45 0.6,-0.4
  region: 0.45,-0.6 0.45,-0.45 0.4,-0.45 0.4,-0.6
  region: 0.45,-0.45 0.45,-0.6 0.6,-0.6 0.6,-0.45
  region: 0.075,-0.6 -0.075,-0.6 -0.075,-0.65 0.075,-0.65
  region: 0.075,-0.45 0.075,-0.6 0.125,-0.6 0.125,-0.45
  rectangle: -0.075,-0.45 0.075,-0.4
  region: -0.075,-0.6 -0.075,-0.45 -0.125,-0.45 -0.125,-0.6
  region: -0.075,-0.45 -0.075,-0.6 0.075,-0.6 0.075,-0.45
  region: -0.45,-0.6 -0.6,-0.6 -0.6,-0.65 -0.45,-0.65
  region: -0.45,-0.45 -0.45,-0.6 -0.4,-0.6 -0.4,-0.45
  rectangle: -0.6,-0.45 -0.45,-0.4
  region: -0.6,-0.6 -0.6,-0.45 -0.65,-0.45 -0.65,-0.6
  region: -0.6,-0.45 -0.6,-0.6 -0.45,-0.6 -0.45,-0.45
  region: 0.6,-0.075 0.45,-0.075 0.45,-0.125 0.6,-0.125
  region: 0.6,0.075 0.6,-0.075 0.65,-0.075 0.65,0.075
  rectangle: 0.45,0.075 0.6,0.125
  region: 0.45,-0.075 0.45,0.075 0.4,0.075 0.4,-0.075
  region: 0.45,0.075 0.45,-0.075 0.6,-0.075 0.6,0.075
  region: -0.45,-0.075 -0.6,-0.075 -0.6,-0.125 -0.45,-0.125
  region: -0.45,0.075 -0.45,-0.075 -0.4,-0.075 -0.4,0.075
  rectangle: -0.6,0.075 -0.45,0.125
  region: -0.6,-0.075 -0.6,0.075 -0.65,0.075 -0.65,-0.075
  region: -0.6,0.075 -0.6,-0.075 -0.45,-0.075 -0.45,0.075
  region: 0.6,0.45 0.45,0.45 0.45,0.4 0.6,0.4
  region: 0.6,0.6 0.6,0.45 0.65,0.45 0.65,0.6
  rectangle: 0.45,0.6 0.6,0.65
  region: 0.45,0.45 0.45,0.6 0.4,0.6 0.4,0.45
  region: 0.45,0.6 0.45,0.45 0.6,0.45 0.6,0.6
  region: 0.075,0.45 -0.075,0.45 -0.075,0.4 0.075,0.4
  region: 0.075,0.6 0.075,0.45 0.125,0.45 0.125,0.6
  rectangle: -0.075,0.6 0.075,0.65
  region: -0.075,0.45 -0.075,0.6 -0.125,0.6 -0.125,0.45
  region: -0.075,0.6 -0.075,0.45 0.075,0.45 0.075,0.6
  region: -0.45,0.45 -0.6,0.45 -0.6,0.4 -0.45,0.4
  region: -0.45,0.6 -0.45,0.45 -0.4,0.45 -0.4,0.6
  rectangle: -0.6,0.6 -0.45,0.65
  region: -0.6,0.45 -0.6,0.6 -0.65,0.6 -0.65,0.45
  region: -0.6,0.6 -0.6,0.45 -0.45,0.45 -0.45,0.6
Mechanical 13:
  lines w0.1: -0.845,-0.92 0.845,-0.92 0.845,0.92 -0.845,0.92 -0.845,-0.92
Mechanical 15:
  lines w0.1: -0.5,0 0.5,0 ; 0,-0.5 0,0.5 ; -0.945,-1.02 0.945,-1.02 0.945,1.02 -0.945,1.02 -0.945,-1.02
3D body: height 0.68, standoff 0, extent -0.844,-0.919 0.844,0.919

## SMD50P3X3-1.72X1.87-8V [mm] "Micro SMD, 8-Leads, Body 1.87x1.72mm, Pitch 0.5mm, NSC Recommended"
height 0.68
pads (8):
  round 0.265 smd paste-0.132 mask+0.05: A1(-0.5,0.5) A2(0,0.5) A3(0.5,0.5) B1(-0.5,0) B3(0.5,0) C1(-0.5,-0.5) C2(0,-0.5) C3(0.5,-0.5)
Top Overlay:
  circle w0.1: c-0.965,1.04 r0.05
Top Paste:
  circle w0.05: c-0.6,-0.075 r0.025
  circle w0.05: c-0.45,0.075 r0.025
  circle w0.05: c-0.6,0.075 r0.025
  circle w0.05: c-0.45,-0.075 r0.025
  circle w0.05: c-0.075,0.6 r0.025
  circle w0.05: c0.075,0.45 r0.025
  circle w0.05: c0.075,0.6 r0.025
  circle w0.05: c-0.075,0.45 r0.025
  circle w0.05: c0.6,0.075 r0.025
  circle w0.05: c0.45,-0.075 r0.025
  circle w0.05: c0.6,-0.075 r0.025
  circle w0.05: c0.45,0.075 r0.025
  circle w0.05: c0.075,-0.6 r0.025
  circle w0.05: c-0.075,-0.45 r0.025
  circle w0.05: c-0.075,-0.6 r0.025
  circle w0.05: c0.075,-0.45 r0.025
  circle w0.05: c0.45,0.45 r0.025
  circle w0.05: c0.6,0.6 r0.025
  circle w0.05: c0.6,0.45 r0.025
  circle w0.05: c0.45,0.6 r0.025
  circle w0.05: c-0.45,0.45 r0.025
  circle w0.05: c-0.6,0.6 r0.025
  circle w0.05: c-0.45,0.6 r0.025
  circle w0.05: c-0.6,0.45 r0.025
  circle w0.05: c-0.45,-0.45 r0.025
  circle w0.05: c-0.6,-0.6 r0.025
  circle w0.05: c-0.6,-0.45 r0.025
  circle w0.05: c-0.45,-0.6 r0.025
  circle w0.05: c0.45,-0.45 r0.025
  circle w0.05: c0.6,-0.6 r0.025
  circle w0.05: c0.45,-0.6 r0.025
  circle w0.05: c0.6,-0.45 r0.025
  region: -0.45,0.075 -0.45,-0.075 -0.4,-0.075 -0.4,0.075
  rectangle: -0.6,0.075 -0.45,0.125
  region: -0.6,-0.075 -0.6,0.075 -0.65,0.075 -0.65,-0.075
  region: -0.45,-0.075 -0.6,-0.075 -0.6,-0.125 -0.45,-0.125
  rectangle: -0.6,-0.075 -0.45,0.075
  region: 0.075,0.45 -0.075,0.45 -0.075,0.4 0.075,0.4
  region: 0.075,0.6 0.075,0.45 0.125,0.45 0.125,0.6
  rectangle: -0.075,0.6 0.075,0.65
  region: -0.075,0.45 -0.075,0.6 -0.125,0.6 -0.125,0.45
  region: -0.075,0.6 -0.075,0.45 0.075,0.45 0.075,0.6
  region: 0.45,-0.075 0.45,0.075 0.4,0.075 0.4,-0.075
  region: 0.6,-0.075 0.45,-0.075 0.45,-0.125 0.6,-0.125
  region: 0.6,0.075 0.6,-0.075 0.65,-0.075 0.65,0.075
  rectangle: 0.45,0.075 0.6,0.125
  region: 0.6,0.075 0.45,0.075 0.45,-0.075 0.6,-0.075
  rectangle: -0.075,-0.45 0.075,-0.4
  region: -0.075,-0.6 -0.075,-0.45 -0.125,-0.45 -0.125,-0.6
  region: 0.075,-0.6 -0.075,-0.6 -0.075,-0.65 0.075,-0.65
  region: 0.075,-0.45 0.075,-0.6 0.125,-0.6 0.125,-0.45
  region: 0.075,-0.6 0.075,-0.45 -0.075,-0.45 -0.075,-0.6
  region: 0.45,0.6 0.45,0.45 0.6,0.45 0.6,0.6
  region: 0.45,0.45 0.45,0.6 0.4,0.6 0.4,0.45
  rectangle: 0.45,0.6 0.6,0.65
  region: 0.6,0.6 0.6,0.45 0.65,0.45 0.65,0.6
  region: 0.6,0.45 0.45,0.45 0.45,0.4 0.6,0.4
  rectangle: -0.6,0.45 -0.45,0.6
  region: -0.45,0.45 -0.6,0.45 -0.6,0.4 -0.45,0.4
  region: -0.6,0.45 -0.6,0.6 -0.65,0.6 -0.65,0.45
  rectangle: -0.6,0.6 -0.45,0.65
  region: -0.45,0.6 -0.45,0.45 -0.4,0.45 -0.4,0.6
  region: -0.45,-0.6 -0.45,-0.45 -0.6,-0.45 -0.6,-0.6
  region: -0.45,-0.45 -0.45,-0.6 -0.4,-0.6 -0.4,-0.45
  region: -0.45,-0.6 -0.6,-0.6 -0.6,-0.65 -0.45,-0.65
  region: -0.6,-0.6 -0.6,-0.45 -0.65,-0.45 -0.65,-0.6
  rectangle: -0.6,-0.45 -0.45,-0.4
  region: 0.6,-0.45 0.45,-0.45 0.45,-0.6 0.6,-0.6
  rectangle: 0.45,-0.45 0.6,-0.4
  region: 0.6,-0.45 0.6,-0.6 0.65,-0.6 0.65,-0.45
  region: 0.6,-0.6 0.45,-0.6 0.45,-0.65 0.6,-0.65
  region: 0.45,-0.6 0.45,-0.45 0.4,-0.45 0.4,-0.6
Mechanical 13:
  lines w0.1: -0.86,-0.935 0.86,-0.935 0.86,0.935 -0.86,0.935 -0.86,-0.935
Mechanical 15:
  lines w0.1: -0.96,-1.035 0.96,-1.035 0.96,1.035 -0.96,1.035 -0.958,-1.035 ; -0.5,0 0.5,0 ; 0,-0.5 0,0.5
3D body: height 0.68, standoff 0, extent -0.859,-0.934 0.859,0.934

## SMD50P3X3-1.92X1.92-8V [mm] "Micro SMD, 8-Leads, Body 1.92x1.92mm, Pitch 0.5mm, NSC Recommended"
height 0.68
pads (8):
  round 0.265 smd paste-0.132 mask+0.05: A1(-0.5,0.5) A2(0,0.5) A3(0.5,0.5) B1(-0.5,0) B3(0.5,0) C1(-0.5,-0.5) C2(0,-0.5) C3(0.5,-0.5)
Top Overlay:
  circle w0.1: c-1.065,1.065 r0.05
Top Paste:
  circle w0.05: c-0.6,0.45 r0.025
  circle w0.05: c-0.45,0.6 r0.025
  circle w0.05: c-0.45,0.45 r0.025
  circle w0.05: c-0.6,0.6 r0.025
  circle w0.05: c-0.075,0.45 r0.025
  circle w0.05: c0.075,0.6 r0.025
  circle w0.05: c0.075,0.45 r0.025
  circle w0.05: c-0.075,0.6 r0.025
  circle w0.05: c0.45,0.45 r0.025
  circle w0.05: c0.6,0.6 r0.025
  circle w0.05: c0.6,0.45 r0.025
  circle w0.05: c0.45,0.6 r0.025
  circle w0.05: c-0.6,-0.075 r0.025
  circle w0.05: c-0.45,0.075 r0.025
  circle w0.05: c-0.45,-0.075 r0.025
  circle w0.05: c-0.6,0.075 r0.025
  circle w0.05: c0.45,-0.075 r0.025
  circle w0.05: c0.6,0.075 r0.025
  circle w0.05: c0.6,-0.075 r0.025
  circle w0.05: c0.45,0.075 r0.025
  circle w0.05: c-0.6,-0.6 r0.025
  circle w0.05: c-0.45,-0.45 r0.025
  circle w0.05: c-0.45,-0.6 r0.025
  circle w0.05: c-0.6,-0.45 r0.025
  circle w0.05: c-0.075,-0.6 r0.025
  circle w0.05: c0.075,-0.45 r0.025
  circle w0.05: c0.075,-0.6 r0.025
  circle w0.05: c-0.075,-0.45 r0.025
  circle w0.05: c0.45,-0.6 r0.025
  circle w0.05: c0.6,-0.45 r0.025
  circle w0.05: c0.6,-0.6 r0.025
  circle w0.05: c0.45,-0.45 r0.025
  region: -0.6,0.6 -0.6,0.45 -0.45,0.45 -0.45,0.6
  region: -0.6,0.45 -0.6,0.6 -0.65,0.6 -0.65,0.45
  rectangle: -0.6,0.6 -0.45,0.65
  region: -0.45,0.6 -0.45,0.45 -0.4,0.45 -0.4,0.6
  region: -0.45,0.45 -0.6,0.45 -0.6,0.4 -0.45,0.4
  region: -0.075,0.6 -0.075,0.45 0.075,0.45 0.075,0.6
  region: -0.075,0.45 -0.075,0.6 -0.125,0.6 -0.125,0.45
  rectangle: -0.075,0.6 0.075,0.65
  region: 0.075,0.6 0.075,0.45 0.125,0.45 0.125,0.6
  region: 0.075,0.45 -0.075,0.45 -0.075,0.4 0.075,0.4
  region: 0.45,0.6 0.45,0.45 0.6,0.45 0.6,0.6
  region: 0.45,0.45 0.45,0.6 0.4,0.6 0.4,0.45
  rectangle: 0.45,0.6 0.6,0.65
  region: 0.6,0.6 0.6,0.45 0.65,0.45 0.65,0.6
  region: 0.6,0.45 0.45,0.45 0.45,0.4 0.6,0.4
  region: -0.6,0.075 -0.6,-0.075 -0.45,-0.075 -0.45,0.075
  region: -0.6,-0.075 -0.6,0.075 -0.65,0.075 -0.65,-0.075
  rectangle: -0.6,0.075 -0.45,0.125
  region: -0.45,0.075 -0.45,-0.075 -0.4,-0.075 -0.4,0.075
  region: -0.45,-0.075 -0.6,-0.075 -0.6,-0.125 -0.45,-0.125
  region: 0.45,0.075 0.45,-0.075 0.6,-0.075 0.6,0.075
  region: 0.45,-0.075 0.45,0.075 0.4,0.075 0.4,-0.075
  rectangle: 0.45,0.075 0.6,0.125
  region: 0.6,0.075 0.6,-0.075 0.65,-0.075 0.65,0.075
  region: 0.6,-0.075 0.45,-0.075 0.45,-0.125 0.6,-0.125
  region: -0.6,-0.45 -0.6,-0.6 -0.45,-0.6 -0.45,-0.45
  region: -0.6,-0.6 -0.6,-0.45 -0.65,-0.45 -0.65,-0.6
  rectangle: -0.6,-0.45 -0.45,-0.4
  region: -0.45,-0.45 -0.45,-0.6 -0.4,-0.6 -0.4,-0.45
  region: -0.45,-0.6 -0.6,-0.6 -0.6,-0.65 -0.45,-0.65
  region: -0.075,-0.45 -0.075,-0.6 0.075,-0.6 0.075,-0.45
  region: -0.075,-0.6 -0.075,-0.45 -0.125,-0.45 -0.125,-0.6
  rectangle: -0.075,-0.45 0.075,-0.4
  region: 0.075,-0.45 0.075,-0.6 0.125,-0.6 0.125,-0.45
  region: 0.075,-0.6 -0.075,-0.6 -0.075,-0.65 0.075,-0.65
  region: 0.45,-0.45 0.45,-0.6 0.6,-0.6 0.6,-0.45
  region: 0.45,-0.6 0.45,-0.45 0.4,-0.45 0.4,-0.6
  rectangle: 0.45,-0.45 0.6,-0.4
  region: 0.6,-0.45 0.6,-0.6 0.65,-0.6 0.65,-0.45
  region: 0.6,-0.6 0.45,-0.6 0.45,-0.65 0.6,-0.65
Mechanical 13:
  lines w0.1: -0.96,-0.96 -0.96,0.96 0.96,0.96 0.96,-0.96 -0.96,-0.96
Mechanical 15:
  lines w0.1: -0.5,0 0.5,0 ; 0,-0.5 0,0.5 ; -1.06,-1.06 -1.06,1.06 1.06,1.06 1.06,-1.06 -1.06,-1.06
3D body: height 0.68, standoff 0, extent -0.96,-0.96 0.96,0.96

## SMD50P3X3-1.95X1.95-9V [mm] "Micro SMD, 9-Leads, Body 1.95x1.95mm, Pitch 0.5mm, NSC Recommended"
height 0.68
pads (9):
  round 0.265 smd paste-0.132 mask+0.05: A1(-0.5,0.5) A2(0,0.5) A3(0.5,0.5) B1(-0.5,0) B2(0,0) B3(0.5,0) C1(-0.5,-0.5) C2(0,-0.5) C3(0.5,-0.5)
Top Overlay:
  circle w0.1: c-1.08,1.08 r0.05
Top Paste:
  circle w0.05: c-0.6,0.45 r0.025
  circle w0.05: c-0.45,0.6 r0.025
  circle w0.05: c-0.45,0.45 r0.025
  circle w0.05: c-0.6,0.6 r0.025
  circle w0.05: c-0.075,0.45 r0.025
  circle w0.05: c0.075,0.6 r0.025
  circle w0.05: c0.075,0.45 r0.025
  circle w0.05: c-0.075,0.6 r0.025
  circle w0.05: c0.45,0.45 r0.025
  circle w0.05: c0.6,0.6 r0.025
  circle w0.05: c0.6,0.45 r0.025
  circle w0.05: c0.45,0.6 r0.025
  circle w0.05: c-0.6,-0.075 r0.025
  circle w0.05: c-0.45,0.075 r0.025
  circle w0.05: c-0.45,-0.075 r0.025
  circle w0.05: c-0.6,0.075 r0.025
  circle w0.05: c-0.075,-0.075 r0.025
  circle w0.05: c0.075,0.075 r0.025
  circle w0.05: c0.075,-0.075 r0.025
  circle w0.05: c-0.075,0.075 r0.025
  circle w0.05: c0.45,-0.075 r0.025
  circle w0.05: c0.6,0.075 r0.025
  circle w0.05: c0.6,-0.075 r0.025
  circle w0.05: c0.45,0.075 r0.025
  circle w0.05: c-0.6,-0.6 r0.025
  circle w0.05: c-0.45,-0.45 r0.025
  circle w0.05: c-0.45,-0.6 r0.025
  circle w0.05: c-0.6,-0.45 r0.025
  circle w0.05: c-0.075,-0.6 r0.025
  circle w0.05: c0.075,-0.45 r0.025
  circle w0.05: c0.075,-0.6 r0.025
  circle w0.05: c-0.075,-0.45 r0.025
  circle w0.05: c0.45,-0.6 r0.025
  circle w0.05: c0.6,-0.45 r0.025
  circle w0.05: c0.6,-0.6 r0.025
  circle w0.05: c0.45,-0.45 r0.025
  region: -0.6,0.6 -0.6,0.45 -0.45,0.45 -0.45,0.6
  region: -0.6,0.45 -0.6,0.6 -0.65,0.6 -0.65,0.45
  rectangle: -0.6,0.6 -0.45,0.65
  region: -0.45,0.6 -0.45,0.45 -0.4,0.45 -0.4,0.6
  region: -0.45,0.45 -0.6,0.45 -0.6,0.4 -0.45,0.4
  region: -0.075,0.6 -0.075,0.45 0.075,0.45 0.075,0.6
  region: -0.075,0.45 -0.075,0.6 -0.125,0.6 -0.125,0.45
  rectangle: -0.075,0.6 0.075,0.65
  region: 0.075,0.6 0.075,0.45 0.125,0.45 0.125,0.6
  region: 0.075,0.45 -0.075,0.45 -0.075,0.4 0.075,0.4
  region: 0.45,0.6 0.45,0.45 0.6,0.45 0.6,0.6
  region: 0.45,0.45 0.45,0.6 0.4,0.6 0.4,0.45
  rectangle: 0.45,0.6 0.6,0.65
  region: 0.6,0.6 0.6,0.45 0.65,0.45 0.65,0.6
  region: 0.6,0.45 0.45,0.45 0.45,0.4 0.6,0.4
  region: -0.6,0.075 -0.6,-0.075 -0.45,-0.075 -0.45,0.075
  region: -0.6,-0.075 -0.6,0.075 -0.65,0.075 -0.65,-0.075
  rectangle: -0.6,0.075 -0.45,0.125
  region: -0.45,0.075 -0.45,-0.075 -0.4,-0.075 -0.4,0.075
  region: -0.45,-0.075 -0.6,-0.075 -0.6,-0.125 -0.45,-0.125
  region: -0.075,0.075 -0.075,-0.075 0.075,-0.075 0.075,0.075
  region: -0.075,-0.075 -0.075,0.075 -0.125,0.075 -0.125,-0.075
  rectangle: -0.075,0.075 0.075,0.125
  region: 0.075,0.075 0.075,-0.075 0.125,-0.075 0.125,0.075
  region: 0.075,-0.075 -0.075,-0.075 -0.075,-0.125 0.075,-0.125
  region: 0.45,0.075 0.45,-0.075 0.6,-0.075 0.6,0.075
  region: 0.45,-0.075 0.45,0.075 0.4,0.075 0.4,-0.075
  rectangle: 0.45,0.075 0.6,0.125
  region: 0.6,0.075 0.6,-0.075 0.65,-0.075 0.65,0.075
  region: 0.6,-0.075 0.45,-0.075 0.45,-0.125 0.6,-0.125
  region: -0.6,-0.45 -0.6,-0.6 -0.45,-0.6 -0.45,-0.45
  region: -0.6,-0.6 -0.6,-0.45 -0.65,-0.45 -0.65,-0.6
  rectangle: -0.6,-0.45 -0.45,-0.4
  region: -0.45,-0.45 -0.45,-0.6 -0.4,-0.6 -0.4,-0.45
  region: -0.45,-0.6 -0.6,-0.6 -0.6,-0.65 -0.45,-0.65
  region: -0.075,-0.45 -0.075,-0.6 0.075,-0.6 0.075,-0.45
  region: -0.075,-0.6 -0.075,-0.45 -0.125,-0.45 -0.125,-0.6
  rectangle: -0.075,-0.45 0.075,-0.4
  region: 0.075,-0.45 0.075,-0.6 0.125,-0.6 0.125,-0.45
  region: 0.075,-0.6 -0.075,-0.6 -0.075,-0.65 0.075,-0.65
  region: 0.45,-0.45 0.45,-0.6 0.6,-0.6 0.6,-0.45
  region: 0.45,-0.6 0.45,-0.45 0.4,-0.45 0.4,-0.6
  rectangle: 0.45,-0.45 0.6,-0.4
  region: 0.6,-0.45 0.6,-0.6 0.65,-0.6 0.65,-0.45
  region: 0.6,-0.6 0.45,-0.6 0.45,-0.65 0.6,-0.65
Mechanical 13:
  lines w0.1: -0.975,-0.975 -0.975,0.975 0.975,0.975 0.975,-0.975 -0.975,-0.975
Mechanical 15:
  lines w0.1: -0.5,0 0.5,0 ; 0,-0.5 0,0.5 ; -1.075,-1.075 -1.075,1.075 1.075,1.075 1.075,-1.075 -1.075,-1.075
3D body: height 0.68, standoff 0, extent -0.975,-0.975 0.975,0.975

## SMD50P3X3_1.52X1.52-8V [mm] "Micro SMD, 8-Leads, Body 1.52x1.52mm, Pitch 0.5mm, NSC Recommended"
height 0.68
pads (8):
  round 0.265 smd paste-0.132 mask+0.05: A1(-0.5,0.5) A2(0,0.5) A3(0.5,0.5) B1(-0.5,0) B3(0.5,0) C1(-0.5,-0.5) C2(0,-0.5) C3(0.5,-0.5)
Top Overlay:
  circle w0.1: c-0.865,0.865 r0.05
Top Paste:
  circle w0.05: c-0.075,-0.6 r0.025
  circle w0.05: c0.075,-0.45 r0.025
  circle w0.05: c-0.075,-0.45 r0.025
  circle w0.05: c0.075,-0.6 r0.025
  circle w0.05: c0.45,-0.075 r0.025
  circle w0.05: c0.6,0.075 r0.025
  circle w0.05: c0.45,0.075 r0.025
  circle w0.05: c0.6,-0.075 r0.025
  circle w0.05: c-0.6,-0.075 r0.025
  circle w0.05: c-0.45,0.075 r0.025
  circle w0.05: c-0.6,0.075 r0.025
  circle w0.05: c-0.45,-0.075 r0.025
  circle w0.05: c-0.075,0.45 r0.025
  circle w0.05: c0.075,0.6 r0.025
  circle w0.05: c-0.075,0.6 r0.025
  circle w0.05: c0.075,0.45 r0.025
  circle w0.05: c-0.6,0.45 r0.025
  circle w0.05: c-0.45,0.6 r0.025
  circle w0.05: c-0.6,0.6 r0.025
  circle w0.05: c-0.45,0.45 r0.025
  circle w0.05: c0.45,0.45 r0.025
  circle w0.05: c0.6,0.6 r0.025
  circle w0.05: c0.45,0.6 r0.025
  circle w0.05: c0.6,0.45 r0.025
  circle w0.05: c-0.6,-0.6 r0.025
  circle w0.05: c-0.45,-0.45 r0.025
  circle w0.05: c-0.6,-0.45 r0.025
  circle w0.05: c-0.45,-0.6 r0.025
  circle w0.05: c0.45,-0.6 r0.025
  circle w0.05: c0.6,-0.45 r0.025
  circle w0.05: c0.45,-0.45 r0.025
  circle w0.05: c0.6,-0.6 r0.025
  region: 0.075,-0.45 0.075,-0.6 0.125,-0.6 0.125,-0.45
  rectangle: -0.075,-0.45 0.075,-0.4
  region: -0.075,-0.6 -0.075,-0.45 -0.125,-0.45 -0.125,-0.6
  region: 0.075,-0.6 -0.075,-0.6 -0.075,-0.65 0.075,-0.65
  rectangle: -0.075,-0.6 0.075,-0.45
  region: 0.6,0.075 0.6,-0.075 0.65,-0.075 0.65,0.075
  rectangle: 0.45,0.075 0.6,0.125
  region: 0.45,-0.075 0.45,0.075 0.4,0.075 0.4,-0.075
  region: 0.6,-0.075 0.45,-0.075 0.45,-0.125 0.6,-0.125
  rectangle: 0.45,-0.075 0.6,0.075
  region: -0.45,0.075 -0.45,-0.075 -0.4,-0.075 -0.4,0.075
  rectangle: -0.6,0.075 -0.45,0.125
  region: -0.6,-0.075 -0.6,0.075 -0.65,0.075 -0.65,-0.075
  region: -0.45,-0.075 -0.6,-0.075 -0.6,-0.125 -0.45,-0.125
  rectangle: -0.6,-0.075 -0.45,0.075
  region: 0.075,0.6 0.075,0.45 0.125,0.45 0.125,0.6
  rectangle: -0.075,0.6 0.075,0.65
  region: -0.075,0.45 -0.075,0.6 -0.125,0.6 -0.125,0.45
  region: 0.075,0.45 -0.075,0.45 -0.075,0.4 0.075,0.4
  rectangle: -0.075,0.45 0.075,0.6
  region: -0.45,0.6 -0.45,0.45 -0.4,0.45 -0.4,0.6
  rectangle: -0.6,0.6 -0.45,0.65
  region: -0.6,0.45 -0.6,0.6 -0.65,0.6 -0.65,0.45
  region: -0.45,0.45 -0.6,0.45 -0.6,0.4 -0.45,0.4
  rectangle: -0.6,0.45 -0.45,0.6
  region: 0.6,0.6 0.6,0.45 0.65,0.45 0.65,0.6
  rectangle: 0.45,0.6 0.6,0.65
  region: 0.45,0.45 0.45,0.6 0.4,0.6 0.4,0.45
  region: 0.6,0.45 0.45,0.45 0.45,0.4 0.6,0.4
  rectangle: 0.45,0.45 0.6,0.6
  region: -0.45,-0.45 -0.45,-0.6 -0.4,-0.6 -0.4,-0.45
  rectangle: -0.6,-0.45 -0.45,-0.4
  region: -0.6,-0.6 -0.6,-0.45 -0.65,-0.45 -0.65,-0.6
  region: -0.45,-0.6 -0.6,-0.6 -0.6,-0.65 -0.45,-0.65
  rectangle: -0.6,-0.6 -0.45,-0.45
  region: 0.6,-0.45 0.6,-0.6 0.65,-0.6 0.65,-0.45
  rectangle: 0.45,-0.45 0.6,-0.4
  region: 0.45,-0.6 0.45,-0.45 0.4,-0.45 0.4,-0.6
  region: 0.6,-0.6 0.45,-0.6 0.45,-0.65 0.6,-0.65
  rectangle: 0.45,-0.6 0.6,-0.45
Mechanical 13:
  lines w0.1: -0.76,-0.76 -0.76,0.76 0.76,0.76 0.76,-0.76 -0.76,-0.76
Mechanical 15:
  lines w0.1: -0.5,0 0.5,0 ; 0,-0.5 0,0.5 ; -0.86,-0.86 -0.86,0.86 0.86,0.86 0.86,-0.86 -0.86,-0.86
3D body: height 0.68, standoff 0, extent -0.759,-0.759 0.759,0.759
